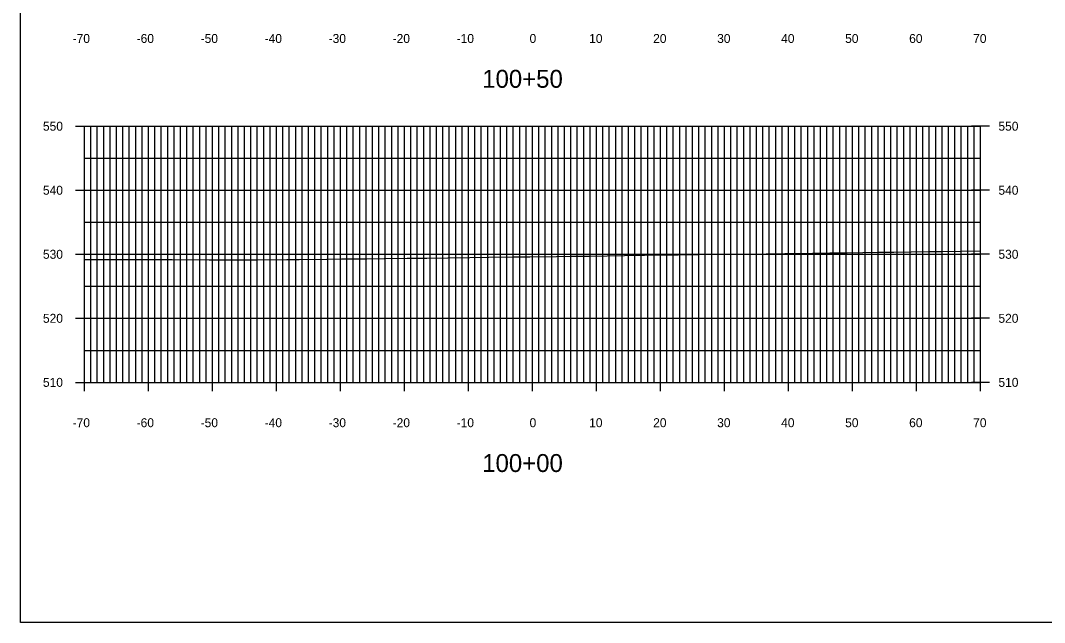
# Model space of a CAD drawing. Extents: x 1509063 to 1512863, y 401160 to 402918.
# Drawn here: x 1511102.7 to 1511262.7, y 402252.1 to 402346.1 of the extents above; entities that cross this region are included whole.
import ezdxf

# ---------------------------------------------------------------- set-up
doc = ezdxf.new("R2010")
doc.units = 0
for name, color, linetype in [('NBL1', 7, 'Continuous'), ('XAX_P', 7, 'Continuous'), ('XAXTIC_P', 7, 'Continuous'), ('XAXTXT_P_T', 7, 'Continuous'), ('XGL_P', 7, 'Continuous'), ('XSLOG', 7, 'Continuous')]:
    doc.layers.add(name, color=color, linetype=linetype)

msp = doc.modelspace()

# ---------------------------------------------------------------- linework, layer by layer
at = {"layer": 'NBL1'}
msp.add_lwpolyline([(1511422.73, 402252.08), (1511102.73, 402252.08), (1511102.73, 402462.08), (1511422.73, 402462.08)], close=True, dxfattribs=at)
at = {"layer": 'XAX_P'}
for p, q in [((1511112.73, 402289.58), (1511112.73, 402329.58)), ((1511182.73, 402289.58), (1511182.73, 402329.58)), ((1511252.73, 402289.58), (1511252.73, 402329.58)), ((1511112.73, 402289.58), (1511252.73, 402289.58))]:
    msp.add_line(p, q, dxfattribs=at)
at = {"layer": 'XAXTIC_P'}
for p, q in [((1511111.33, 402329.58), (1511114.13, 402329.58)), ((1511181.33, 402329.58), (1511184.13, 402329.58)), ((1511254.13, 402329.58), (1511251.33, 402329.58)), ((1511111.33, 402319.58), (1511114.13, 402319.58)), ((1511181.33, 402319.58), (1511184.13, 402319.58)), ((1511254.13, 402319.58), (1511251.33, 402319.58)), ((1511111.33, 402309.58), (1511114.13, 402309.58)), ((1511181.33, 402309.58), (1511184.13, 402309.58)), ((1511254.13, 402309.58), (1511251.33, 402309.58)), ((1511111.33, 402299.58), (1511114.13, 402299.58)), ((1511181.33, 402299.58), (1511184.13, 402299.58)), ((1511254.13, 402299.58), (1511251.33, 402299.58)), ((1511112.73, 402288.18), (1511112.73, 402290.98)), ((1511122.73, 402288.18), (1511122.73, 402290.98)), ((1511132.73, 402288.18), (1511132.73, 402290.98)), ((1511142.73, 402288.18), (1511142.73, 402290.98)), ((1511152.73, 402288.18), (1511152.73, 402290.98)), ((1511162.73, 402288.18), (1511162.73, 402290.98)), ((1511172.73, 402288.18), (1511172.73, 402290.98)), ((1511182.73, 402288.18), (1511182.73, 402290.98)), ((1511192.73, 402288.18), (1511192.73, 402290.98)), ((1511202.73, 402288.18), (1511202.73, 402290.98)), ((1511212.73, 402288.18), (1511212.73, 402290.98)), ((1511222.73, 402288.18), (1511222.73, 402290.98)), ((1511232.73, 402288.18), (1511232.73, 402290.98)), ((1511242.73, 402288.18), (1511242.73, 402290.98)), ((1511252.73, 402288.18), (1511252.73, 402290.98)), ((1511111.33, 402289.58), (1511114.13, 402289.58)), ((1511181.33, 402289.58), (1511184.13, 402289.58)), ((1511254.13, 402289.58), (1511251.33, 402289.58))]:
    msp.add_line(p, q, dxfattribs=at)
at = {"layer": 'XGL_P'}
for p, q in [((1511112.73, 402329.58), (1511252.73, 402329.58)), ((1511112.73, 402289.58), (1511112.73, 402329.58)), ((1511113.73, 402289.58), (1511113.73, 402329.58)), ((1511114.73, 402289.58), (1511114.73, 402329.58)), ((1511115.73, 402289.58), (1511115.73, 402329.58)), ((1511116.73, 402289.58), (1511116.73, 402329.58)), ((1511117.73, 402289.58), (1511117.73, 402329.58)), ((1511118.73, 402289.58), (1511118.73, 402329.58)), ((1511119.73, 402289.58), (1511119.73, 402329.58)), ((1511120.73, 402289.58), (1511120.73, 402329.58)), ((1511121.73, 402289.58), (1511121.73, 402329.58)), ((1511122.73, 402289.58), (1511122.73, 402329.58)), ((1511123.73, 402289.58), (1511123.73, 402329.58)), ((1511124.73, 402289.58), (1511124.73, 402329.58)), ((1511125.73, 402289.58), (1511125.73, 402329.58)), ((1511126.73, 402289.58), (1511126.73, 402329.58)), ((1511127.73, 402289.58), (1511127.73, 402329.58)), ((1511128.73, 402289.58), (1511128.73, 402329.58)), ((1511129.73, 402289.58), (1511129.73, 402329.58)), ((1511130.73, 402289.58), (1511130.73, 402329.58)), ((1511131.73, 402289.58), (1511131.73, 402329.58)), ((1511132.73, 402289.58), (1511132.73, 402329.58)), ((1511133.73, 402289.58), (1511133.73, 402329.58)), ((1511134.73, 402289.58), (1511134.73, 402329.58)), ((1511135.73, 402289.58), (1511135.73, 402329.58)), ((1511136.73, 402289.58), (1511136.73, 402329.58)), ((1511137.73, 402289.58), (1511137.73, 402329.58)), ((1511138.73, 402289.58), (1511138.73, 402329.58)), ((1511139.73, 402289.58), (1511139.73, 402329.58)), ((1511140.73, 402289.58), (1511140.73, 402329.58)), ((1511141.73, 402289.58), (1511141.73, 402329.58)), ((1511142.73, 402289.58), (1511142.73, 402329.58)), ((1511143.73, 402289.58), (1511143.73, 402329.58)), ((1511144.73, 402289.58), (1511144.73, 402329.58)), ((1511145.73, 402289.58), (1511145.73, 402329.58)), ((1511146.73, 402289.58), (1511146.73, 402329.58)), ((1511147.73, 402289.58), (1511147.73, 402329.58)), ((1511148.73, 402289.58), (1511148.73, 402329.58)), ((1511149.73, 402289.58), (1511149.73, 402329.58)), ((1511150.73, 402289.58), (1511150.73, 402329.58)), ((1511151.73, 402289.58), (1511151.73, 402329.58)), ((1511152.73, 402289.58), (1511152.73, 402329.58)), ((1511153.73, 402289.58), (1511153.73, 402329.58)), ((1511154.73, 402289.58), (1511154.73, 402329.58)), ((1511155.73, 402289.58), (1511155.73, 402329.58)), ((1511156.73, 402289.58), (1511156.73, 402329.58)), ((1511157.73, 402289.58), (1511157.73, 402329.58)), ((1511158.73, 402289.58), (1511158.73, 402329.58)), ((1511159.73, 402289.58), (1511159.73, 402329.58)), ((1511160.73, 402289.58), (1511160.73, 402329.58)), ((1511161.73, 402289.58), (1511161.73, 402329.58)), ((1511162.73, 402289.58), (1511162.73, 402329.58)), ((1511163.73, 402289.58), (1511163.73, 402329.58)), ((1511164.73, 402289.58), (1511164.73, 402329.58)), ((1511165.73, 402289.58), (1511165.73, 402329.58)), ((1511166.73, 402289.58), (1511166.73, 402329.58)), ((1511167.73, 402289.58), (1511167.73, 402329.58)), ((1511168.73, 402289.58), (1511168.73, 402329.58)), ((1511169.73, 402289.58), (1511169.73, 402329.58)), ((1511170.73, 402289.58), (1511170.73, 402329.58)), ((1511171.73, 402289.58), (1511171.73, 402329.58)), ((1511172.73, 402289.58), (1511172.73, 402329.58)), ((1511173.73, 402289.58), (1511173.73, 402329.58)), ((1511174.73, 402289.58), (1511174.73, 402329.58)), ((1511175.73, 402289.58), (1511175.73, 402329.58)), ((1511176.73, 402289.58), (1511176.73, 402329.58)), ((1511177.73, 402289.58), (1511177.73, 402329.58)), ((1511178.73, 402289.58), (1511178.73, 402329.58)), ((1511179.73, 402289.58), (1511179.73, 402329.58)), ((1511180.73, 402289.58), (1511180.73, 402329.58)), ((1511181.73, 402289.58), (1511181.73, 402329.58)), ((1511182.73, 402289.58), (1511182.73, 402329.58)), ((1511183.73, 402289.58), (1511183.73, 402329.58)), ((1511184.73, 402289.58), (1511184.73, 402329.58)), ((1511185.73, 402289.58), (1511185.73, 402329.58)), ((1511186.73, 402289.58), (1511186.73, 402329.58)), ((1511187.73, 402289.58), (1511187.73, 402329.58)), ((1511188.73, 402289.58), (1511188.73, 402329.58)), ((1511189.73, 402289.58), (1511189.73, 402329.58)), ((1511190.73, 402289.58), (1511190.73, 402329.58)), ((1511191.73, 402289.58), (1511191.73, 402329.58)), ((1511192.73, 402289.58), (1511192.73, 402329.58)), ((1511193.73, 402289.58), (1511193.73, 402329.58)), ((1511194.73, 402289.58), (1511194.73, 402329.58)), ((1511195.73, 402289.58), (1511195.73, 402329.58)), ((1511196.73, 402289.58), (1511196.73, 402329.58)), ((1511197.73, 402289.58), (1511197.73, 402329.58)), ((1511198.73, 402289.58), (1511198.73, 402329.58)), ((1511199.73, 402289.58), (1511199.73, 402329.58)), ((1511200.73, 402289.58), (1511200.73, 402329.58)), ((1511201.73, 402289.58), (1511201.73, 402329.58)), ((1511202.73, 402289.58), (1511202.73, 402329.58)), ((1511203.73, 402289.58), (1511203.73, 402329.58)), ((1511204.73, 402289.58), (1511204.73, 402329.58)), ((1511205.73, 402289.58), (1511205.73, 402329.58)), ((1511206.73, 402289.58), (1511206.73, 402329.58)), ((1511207.73, 402289.58), (1511207.73, 402329.58)), ((1511208.73, 402289.58), (1511208.73, 402329.58)), ((1511209.73, 402289.58), (1511209.73, 402329.58)), ((1511210.73, 402289.58), (1511210.73, 402329.58)), ((1511211.73, 402289.58), (1511211.73, 402329.58)), ((1511212.73, 402289.58), (1511212.73, 402329.58)), ((1511213.73, 402289.58), (1511213.73, 402329.58)), ((1511214.73, 402289.58), (1511214.73, 402329.58)), ((1511215.73, 402289.58), (1511215.73, 402329.58)), ((1511216.73, 402289.58), (1511216.73, 402329.58)), ((1511217.73, 402289.58), (1511217.73, 402329.58)), ((1511218.73, 402289.58), (1511218.73, 402329.58)), ((1511219.73, 402289.58), (1511219.73, 402329.58)), ((1511220.73, 402289.58), (1511220.73, 402329.58)), ((1511221.73, 402289.58), (1511221.73, 402329.58)), ((1511222.73, 402289.58), (1511222.73, 402329.58)), ((1511223.73, 402289.58), (1511223.73, 402329.58)), ((1511224.73, 402289.58), (1511224.73, 402329.58)), ((1511225.73, 402289.58), (1511225.73, 402329.58)), ((1511226.73, 402289.58), (1511226.73, 402329.58)), ((1511227.73, 402289.58), (1511227.73, 402329.58)), ((1511228.73, 402289.58), (1511228.73, 402329.58)), ((1511229.73, 402289.58), (1511229.73, 402329.58)), ((1511230.73, 402289.58), (1511230.73, 402329.58)), ((1511231.73, 402289.58), (1511231.73, 402329.58)), ((1511232.73, 402289.58), (1511232.73, 402329.58)), ((1511233.73, 402289.58), (1511233.73, 402329.58)), ((1511234.73, 402289.58), (1511234.73, 402329.58)), ((1511235.73, 402289.58), (1511235.73, 402329.58)), ((1511236.73, 402289.58), (1511236.73, 402329.58)), ((1511237.73, 402289.58), (1511237.73, 402329.58)), ((1511238.73, 402289.58), (1511238.73, 402329.58)), ((1511239.73, 402289.58), (1511239.73, 402329.58)), ((1511240.73, 402289.58), (1511240.73, 402329.58)), ((1511241.73, 402289.58), (1511241.73, 402329.58)), ((1511242.73, 402289.58), (1511242.73, 402329.58)), ((1511243.73, 402289.58), (1511243.73, 402329.58)), ((1511244.73, 402289.58), (1511244.73, 402329.58)), ((1511245.73, 402289.58), (1511245.73, 402329.58)), ((1511246.73, 402289.58), (1511246.73, 402329.58)), ((1511247.73, 402289.58), (1511247.73, 402329.58)), ((1511248.73, 402289.58), (1511248.73, 402329.58)), ((1511249.73, 402289.58), (1511249.73, 402329.58)), ((1511250.73, 402289.58), (1511250.73, 402329.58)), ((1511251.73, 402289.58), (1511251.73, 402329.58)), ((1511252.73, 402289.58), (1511252.73, 402329.58)), ((1511112.73, 402324.58), (1511252.73, 402324.58)), ((1511112.73, 402319.58), (1511252.73, 402319.58)), ((1511112.73, 402314.58), (1511252.73, 402314.58)), ((1511112.73, 402309.58), (1511252.73, 402309.58)), ((1511112.73, 402304.58), (1511252.73, 402304.58)), ((1511112.73, 402299.58), (1511252.73, 402299.58)), ((1511112.73, 402294.58), (1511252.73, 402294.58)), ((1511112.73, 402289.58), (1511252.73, 402289.58))]:
    msp.add_line(p, q, dxfattribs=at)
at = {"layer": 'XSLOG'}
msp.add_lwpolyline([(1511112.73, 402308.79), (1511113.58, 402308.79), (1511114.63, 402308.79), (1511119.97, 402308.79), (1511120.37, 402308.79), (1511123.94, 402308.79), (1511126.22, 402308.77), (1511126.44, 402308.77), (1511132.21, 402308.73), (1511133.01, 402308.73), (1511138.14, 402308.69), (1511139.64, 402308.71), (1511144.35, 402308.75), (1511146.25, 402308.78), (1511150.59, 402308.82), (1511152.88, 402308.85), (1511156.86, 402308.89), (1511159.54, 402308.92), (1511163.17, 402308.96), (1511166.23, 402309), (1511169.51, 402309.03), (1511172.95, 402309.08), (1511175.89, 402309.11), (1511179.69, 402309.16), (1511182.29, 402309.19), (1511186.46, 402309.25), (1511188.73, 402309.27), (1511191.69, 402309.31), (1511197.11, 402309.39), (1511200.24, 402309.44), (1511205.49, 402309.51), (1511208.79, 402309.56), (1511212.24, 402309.59), (1511215.39, 402309.62), (1511219.23, 402309.67), (1511222.18, 402309.7), (1511226.47, 402309.76), (1511229.2, 402309.79), (1511231.9, 402309.81), (1511236.79, 402309.89), (1511239.17, 402309.92), (1511244.6, 402310), (1511246.66, 402310.03), (1511252.61, 402310.12), (1511252.73, 402310.12)], dxfattribs=at)

# ---------------------------------------------------------------- texts
at = {"layer": 'XAXTXT_P_T'}
for s, height, p in [('-70', 1.4, (1511110.88, 402342.58)), ('-60', 1.4, (1511120.88, 402342.58)), ('-50', 1.4, (1511130.88, 402342.58)), ('-40', 1.4, (1511140.88, 402342.58)), ('-30', 1.4, (1511150.88, 402342.58)), ('-20', 1.4, (1511160.88, 402342.58)), ('-10', 1.4, (1511170.88, 402342.58)), ('0', 1.4, (1511182.27, 402342.58)), ('10', 1.4, (1511191.58, 402342.58)), ('20', 1.4, (1511201.58, 402342.58)), ('30', 1.4, (1511211.58, 402342.58)), ('40', 1.4, (1511221.58, 402342.58)), ('50', 1.4, (1511231.58, 402342.58)), ('60', 1.4, (1511241.58, 402342.58)), ('70', 1.4, (1511251.58, 402342.58)), ('100+50', 2.8, (1511174.87, 402335.58)), ('550', 1.4, (1511106.24, 402328.88)), ('550', 1.4, (1511255.53, 402328.88)), ('540', 1.4, (1511106.24, 402318.88)), ('540', 1.4, (1511255.53, 402318.88)), ('530', 1.4, (1511106.24, 402308.88)), ('530', 1.4, (1511255.53, 402308.88)), ('520', 1.4, (1511106.24, 402298.88)), ('520', 1.4, (1511255.53, 402298.88)), ('510', 1.4, (1511106.24, 402288.88)), ('510', 1.4, (1511255.53, 402288.88)), ('-70', 1.4, (1511110.88, 402282.58)), ('-60', 1.4, (1511120.88, 402282.58)), ('-50', 1.4, (1511130.88, 402282.58)), ('-40', 1.4, (1511140.88, 402282.58)), ('-30', 1.4, (1511150.88, 402282.58)), ('-20', 1.4, (1511160.88, 402282.58)), ('-10', 1.4, (1511170.88, 402282.58)), ('0', 1.4, (1511182.27, 402282.58)), ('10', 1.4, (1511191.58, 402282.58)), ('20', 1.4, (1511201.58, 402282.58)), ('30', 1.4, (1511211.58, 402282.58)), ('40', 1.4, (1511221.58, 402282.58)), ('50', 1.4, (1511231.58, 402282.58)), ('60', 1.4, (1511241.58, 402282.58)), ('70', 1.4, (1511251.58, 402282.58)), ('100+00', 2.8, (1511174.87, 402275.58))]:
    msp.add_text(s, height=height, dxfattribs=at).set_placement(p)

doc.saveas('drawing.dxf')
